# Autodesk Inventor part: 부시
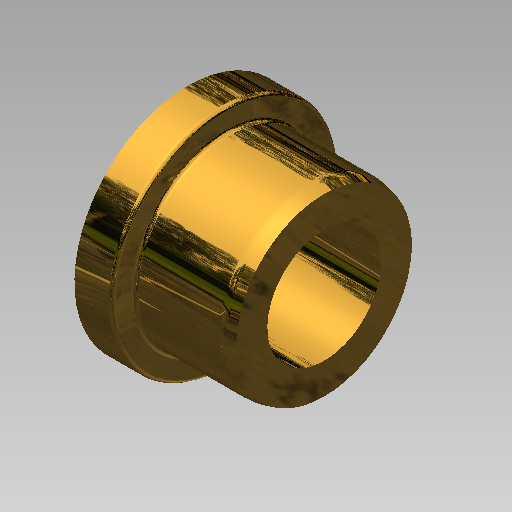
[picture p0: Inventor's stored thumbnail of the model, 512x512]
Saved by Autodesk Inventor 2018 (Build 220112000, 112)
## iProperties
Created: 2016-05
Part Number: 부시
Document SubType Name: Modeling
Designer: mduedu
Density: 7.86 g/cm^3
Material: 강철, 연강
Appearance: 황동 - 새틴
Author: mduedu
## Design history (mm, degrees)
sketch "스케치1"
  geometry: L1 (0, 0)-(18, 0); L2 (1.5, 7.5)-(18, 7.5); L3 (18, 7.5)-(18, 11.598); L4 (16.5, 12)-(5, 12); L5 (5, 12)-(5, 15); L6 (5, 15)-(0, 15); L7 (0, 15)-(0, 7.902); L8 (0, 7.902)-(1.5, 7.5); L9 (16.5, 12)-(18, 11.598)
  constraints: 18 end point, 4 parallel, 1 horizontal, 1 perpendicular, 1 point on line, 1 vertical, 1 vertical alignment
  dimensions: "d0" = 18 distance of L1.start L1.end; "d1" = 15 diameter of L2 L1; "d2" = 24 diameter of L4 L1; "d3" = 5 distance of L5.end L6.end; "d4" = 30 diameter of L6 L1; "d9" = 15 deg angle of L2 L8; "d10" = 1.5 horizontal distance of L7.end L2.start; "d13" = 15 deg angle of L4 L9; "d14" = 1.5 distance from line of L4.start L3
revolve "회전1" sketch "스케치1" stored, may be unused: angle "d5" = 90 deg
fillet "모깎기1" dims "d11" = 4
fillet "모깎기2" dims "d12" = 0.5
node "솔리드1"
